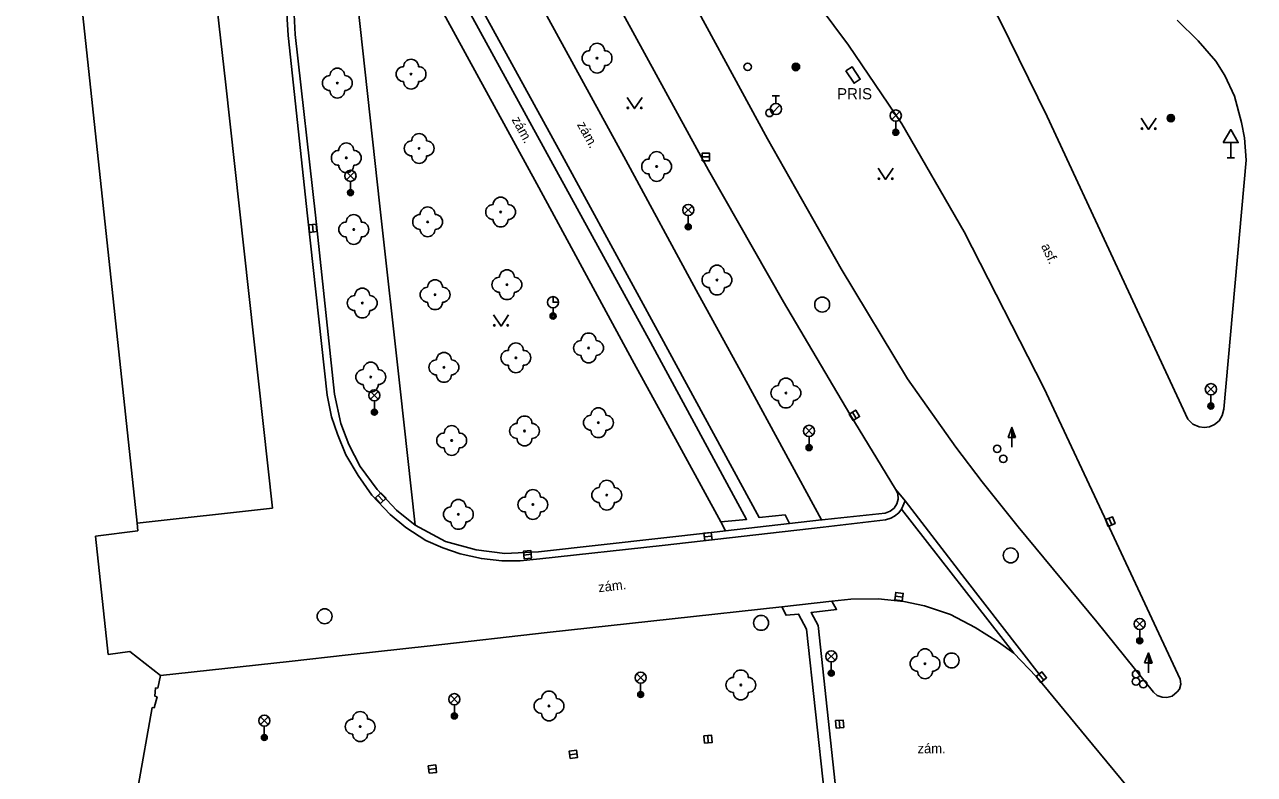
# Model space of a CAD drawing. Extents: x -598341 to -594502, y -1162301 to -1161406.
# Drawn here: x -597714.7 to -597632.3, y -1161626.1 to -1161575.8 of the extents above; entities that cross this region are included whole.
import ezdxf

# ---------------------------------------------------------------- set-up
doc = ezdxf.new("R2010")
doc.units = 0
for name, color, linetype in [('Vrstva 10', 7, 'Continuous'), ('Vrstva 11', 7, 'Continuous'), ('Vrstva 22', 7, 'Continuous'), ('Vrstva 24', 7, 'Continuous'), ('Vrstva 25', 7, 'Continuous'), ('Vrstva 27', 7, 'Continuous'), ('Vrstva 28', 7, 'Continuous'), ('Vrstva 33', 7, 'Continuous'), ('Vrstva 34', 7, 'Continuous'), ('Vrstva 36', 7, 'Continuous'), ('Vrstva 40', 7, 'Continuous'), ('Vrstva 41', 7, 'Continuous'), ('Vrstva 5', 7, 'Continuous')]:
    doc.layers.add(name, color=color, linetype=linetype)

msp = doc.modelspace()

# ---------------------------------------------------------------- linework, layer by layer
at = {"layer": 'Vrstva 10'}
for p, q in [((-597636.78, -1161602.29), (-597646.2, -1161581.99)), ((-597632.87, -1161584.92), (-597634.37, -1161601.62))]:
    msp.add_line(p, q, dxfattribs=at)
for points in [[(-597656.36, -1161606.96), (-597659.42, -1161601.94), (-597663.88, -1161594.41), (-597668.9, -1161585.59), (-597675.27, -1161573.94), (-597680.54, -1161564.05), (-597683.22, -1161558.87), (-597685.33, -1161554.76), (-597687.08, -1161551.17), (-597687.88, -1161549.64)], [(-597639.08, -1161620.57), (-597642.88, -1161615.87), (-597648.14, -1161609.49), (-597650.57, -1161606.47), (-597652.32, -1161604.16), (-597655.57, -1161599.57), (-597660.01, -1161592.2), (-597664.94, -1161583.49), (-597671.35, -1161571.69), (-597676.51, -1161562.01), (-597679.11, -1161556.86), (-597681.15, -1161552.57)], [(-597637.29, -1161619.71), (-597642.03, -1161609.56), (-597646.42, -1161600.19), (-597651.76, -1161589.72), (-597655.95, -1161582.49), (-597659.52, -1161577.23), (-597662.52, -1161573.15), (-597670.61, -1161562.65), (-597678.56, -1161552.49)], [(-597696.59, -1161576.5), (-597696.66, -1161575.16), (-597696.64, -1161573.61), (-597696.52, -1161572.32), (-597696.31, -1161571.01), (-597695.96, -1161569.39), (-597695.44, -1161567.63)], [(-597646.2, -1161581.99), (-597649.35, -1161575.58), (-597652.72, -1161569.3)], [(-597637.51, -1161575.55), (-597636.09, -1161576.92), (-597634.92, -1161578.3), (-597634.31, -1161579.26), (-597633.65, -1161580.63), (-597633.2, -1161582.39), (-597632.99, -1161583.43), (-597632.87, -1161584.92)], [(-597693.95, -1161600.61), (-597695.23, -1161588.62), (-597696.59, -1161576.5)], [(-597688.54, -1161609.38), (-597689.79, -1161608.38), (-597691.1, -1161607), (-597692.23, -1161605.45), (-597693, -1161603.97), (-597693.52, -1161602.56), (-597693.95, -1161600.61)], [(-597636.78, -1161602.29), (-597636.44, -1161602.62), (-597636.02, -1161602.8), (-597635.7, -1161602.84), (-597635.34, -1161602.79), (-597634.99, -1161602.64), (-597634.69, -1161602.39), (-597634.48, -1161602.04), (-597634.37, -1161601.62)], [(-597657.05, -1161608.57), (-597656.73, -1161608.45), (-597656.46, -1161608.24), (-597656.28, -1161607.95), (-597656.19, -1161607.64), (-597656.22, -1161607.26), (-597656.36, -1161606.96)], [(-597661.29, -1161609.03), (-597660.46, -1161608.93), (-597657.05, -1161608.57)], [(-597680.28, -1161611.18), (-597682.54, -1161611.29), (-597684.47, -1161611.03), (-597686.51, -1161610.47), (-597688.54, -1161609.38)], [(-597663.46, -1161609.27), (-597667.76, -1161609.76)], [(-597661.32, -1161609.03), (-597663.46, -1161609.27)], [(-597661.29, -1161609.03), (-597661.32, -1161609.03)], [(-597667.76, -1161609.76), (-597668.7, -1161609.87), (-597672.08, -1161610.26), (-597680.28, -1161611.18)], [(-597660.63, -1161614.48), (-597663.99, -1161614.85)], [(-597659.36, -1161614.35), (-597660.63, -1161614.48)], [(-597659.36, -1161614.35), (-597657.52, -1161614.31), (-597655.81, -1161614.5), (-597654.42, -1161614.78), (-597652.69, -1161615.36), (-597651.04, -1161616.23), (-597649.47, -1161617.22), (-597648.44, -1161617.96)], [(-597663.99, -1161614.85), (-597671.33, -1161615.65), (-597679.7, -1161616.58), (-597687.53, -1161617.48), (-597693.03, -1161618.08), (-597696.99, -1161618.51), (-597705.6, -1161619.45)], [(-597648.44, -1161617.96), (-597646.95, -1161619.53)], [(-597610.91, -1161677.42), (-597615.12, -1161669.99), (-597619.69, -1161661.76), (-597621.87, -1161657.96), (-597626.47, -1161650), (-597632.47, -1161638.84), (-597635.09, -1161634.33), (-597636.33, -1161632.57), (-597638.15, -1161630.21), (-597639.32, -1161628.73), (-597643.16, -1161624.07), (-597646.55, -1161619.99), (-597646.95, -1161619.53)], [(-597639.08, -1161620.57), (-597638.83, -1161620.79), (-597638.5, -1161620.92), (-597638.2, -1161620.93), (-597637.84, -1161620.84), (-597637.51, -1161620.55), (-597637.35, -1161620.37), (-597637.26, -1161620.04), (-597637.29, -1161619.71)]]:
    msp.add_lwpolyline(points, dxfattribs=at)
at = {"layer": 'Vrstva 11'}
for points in [[(-597663.46, -1161609.27), (-597663.76, -1161608.68), (-597665.49, -1161608.87), (-597672.17, -1161596.58), (-597678.7, -1161584.61), (-597685.19, -1161572.76), (-597692.44, -1161559.58), (-597691.74, -1161557.52), (-597692.02, -1161557)], [(-597668.08, -1161609.16), (-597666.34, -1161609), (-597672.77, -1161597.11), (-597679.46, -1161584.95), (-597685.96, -1161573.07), (-597692.73, -1161560.67), (-597693.42, -1161562.71), (-597693.7, -1161562.22)], [(-597669.73, -1161593.64), (-597674.43, -1161584.92), (-597680.24, -1161574.32), (-597685.26, -1161565.17), (-597687.25, -1161561.52)], [(-597697.05, -1161576.58), (-597697.11, -1161575.47), (-597697.09, -1161573.66), (-597696.94, -1161572.13), (-597696.71, -1161570.61), (-597696.34, -1161568.94), (-597695.82, -1161567.29)], [(-597668.08, -1161609.16), (-597671.75, -1161602.42), (-597673.87, -1161598.54), (-597680.39, -1161586.52), (-597686.5, -1161575.37), (-597690.54, -1161567.98), (-597692.96, -1161569.3), (-597692.22, -1161575.97)], [(-597694.44, -1161600.67), (-597695.75, -1161588.66), (-597697.05, -1161576.58)], [(-597688.54, -1161609.38), (-597689.56, -1161600.24), (-597690.92, -1161588), (-597692.22, -1161575.97)], [(-597661.32, -1161609.03), (-597666.38, -1161599.73), (-597669.73, -1161593.64)], [(-597680.19, -1161611.64), (-597681.51, -1161611.78), (-597682.73, -1161611.78), (-597684.11, -1161611.62), (-597685.54, -1161611.31), (-597686.69, -1161610.91), (-597687.82, -1161610.4), (-597689.16, -1161609.55), (-597690.21, -1161608.66), (-597691.45, -1161607.37), (-597692.37, -1161606.06), (-597693.19, -1161604.67), (-597693.75, -1161603.29), (-597694.15, -1161602.12), (-597694.44, -1161600.67)], [(-597655.73, -1161607.76), (-597656.36, -1161606.96)], [(-597655.96, -1161608.31), (-597655.73, -1161607.76)], [(-597646.74, -1161619.37), (-597651.69, -1161612.98), (-597655.73, -1161607.76)], [(-597657.04, -1161609.02), (-597656.68, -1161608.92), (-597656.44, -1161608.79), (-597656.15, -1161608.55), (-597655.96, -1161608.31)], [(-597648.44, -1161617.96), (-597655.96, -1161608.31)], [(-597657.04, -1161609.02), (-597661.22, -1161609.51), (-597672.01, -1161610.74), (-597680.19, -1161611.64)], [(-597667.76, -1161609.76), (-597668.08, -1161609.16)], [(-597659.74, -1161632.93), (-597661.55, -1161616.11), (-597662.02, -1161615.24), (-597660.32, -1161615.03), (-597660.63, -1161614.48)], [(-597659.74, -1161632.93), (-597660.53, -1161632.96), (-597662.33, -1161616.35), (-597662.86, -1161615.34), (-597663.7, -1161615.42), (-597663.99, -1161614.85)], [(-597646.95, -1161619.53), (-597646.74, -1161619.37)]]:
    msp.add_lwpolyline(points, dxfattribs=at)
at = {"layer": 'Vrstva 22'}
for centre in [(-597676.36, -1161578.09), (-597693.76, -1161579.76), (-597688.82, -1161579.16), (-597693.16, -1161584.77), (-597688.28, -1161584.14), (-597672.37, -1161585.35), (-597682.82, -1161588.4), (-597692.66, -1161589.57), (-597687.71, -1161589.06), (-597668.33, -1161592.96), (-597687.21, -1161593.94), (-597682.4, -1161593.27), (-597692.09, -1161594.5), (-597676.93, -1161597.51), (-597686.62, -1161598.81), (-597681.8, -1161598.17), (-597691.52, -1161599.46), (-597663.71, -1161600.53), (-597676.27, -1161602.52), (-597686.1, -1161603.71), (-597681.22, -1161603.07), (-597675.71, -1161607.37), (-597685.65, -1161608.66), (-597680.66, -1161608), (-597654.39, -1161618.67), (-597666.73, -1161620.09), (-597679.58, -1161621.5), (-597692.23, -1161622.88)]:
    msp.add_circle(centre, 0.05, dxfattribs=at)
for centre, start, end in [((-597676.36, -1161577.59), 0, 180), ((-597688.82, -1161578.66), 0, 180), ((-597676.86, -1161578.09), 90, 270), ((-597675.86, -1161578.09), 270, 90), ((-597693.76, -1161579.26), 0, 180), ((-597689.32, -1161579.16), 90, 270), ((-597688.32, -1161579.16), 270, 90), ((-597676.36, -1161578.59), 180, 0), ((-597694.26, -1161579.76), 90, 270), ((-597693.26, -1161579.76), 270, 90), ((-597688.82, -1161579.66), 180, 0), ((-597693.76, -1161580.26), 180, 0), ((-597688.28, -1161583.64), 0, 180), ((-597693.16, -1161584.27), 0, 180), ((-597688.78, -1161584.14), 90, 270), ((-597687.78, -1161584.14), 270, 90), ((-597693.66, -1161584.77), 90, 270), ((-597692.66, -1161584.77), 270, 90), ((-597688.28, -1161584.64), 180, 0), ((-597672.37, -1161584.85), 0, 180), ((-597693.16, -1161585.27), 180, 0), ((-597672.87, -1161585.35), 90, 270), ((-597671.87, -1161585.35), 270, 90), ((-597672.37, -1161585.85), 180, 0), ((-597687.71, -1161588.56), 0, 180), ((-597683.32, -1161588.4), 90, 270), ((-597682.82, -1161587.9), 0, 180), ((-597682.32, -1161588.4), 270, 90), ((-597692.66, -1161589.07), 0, 180), ((-597688.21, -1161589.06), 90, 270), ((-597687.21, -1161589.06), 270, 90), ((-597682.82, -1161588.9), 180, 0), ((-597693.16, -1161589.57), 90, 270), ((-597692.16, -1161589.57), 270, 90), ((-597687.71, -1161589.56), 180, 0), ((-597692.66, -1161590.07), 180, 0), ((-597668.33, -1161592.46), 0, 180), ((-597687.21, -1161593.44), 0, 180), ((-597682.9, -1161593.27), 90, 270), ((-597682.4, -1161592.77), 0, 180), ((-597681.9, -1161593.27), 270, 90), ((-597668.83, -1161592.96), 90, 270), ((-597667.83, -1161592.96), 270, 90), ((-597692.09, -1161594), 0, 180), ((-597687.71, -1161593.94), 90, 270), ((-597686.71, -1161593.94), 270, 90), ((-597682.4, -1161593.77), 180, 0), ((-597668.33, -1161593.46), 180, 0), ((-597692.59, -1161594.5), 90, 270), ((-597691.59, -1161594.5), 270, 90), ((-597687.21, -1161594.44), 180, 0), ((-597692.09, -1161595), 180, 0), ((-597681.8, -1161597.67), 0, 180), ((-597677.43, -1161597.51), 90, 270), ((-597676.93, -1161597.01), 0, 180), ((-597676.43, -1161597.51), 270, 90), ((-597686.62, -1161598.31), 0, 180), ((-597682.3, -1161598.17), 90, 270), ((-597681.3, -1161598.17), 270, 90), ((-597676.93, -1161598.01), 180, 0), ((-597691.52, -1161598.96), 0, 180), ((-597687.12, -1161598.81), 90, 270), ((-597686.12, -1161598.81), 270, 90), ((-597681.8, -1161598.67), 180, 0), ((-597692.02, -1161599.46), 90, 270), ((-597691.02, -1161599.46), 270, 90), ((-597686.62, -1161599.31), 180, 0), ((-597663.71, -1161600.03), 0, 180), ((-597691.52, -1161599.96), 180, 0), ((-597664.21, -1161600.53), 90, 270), ((-597663.21, -1161600.53), 270, 90), ((-597663.71, -1161601.03), 180, 0), ((-597681.22, -1161602.57), 0, 180), ((-597676.77, -1161602.52), 90, 270), ((-597676.27, -1161602.02), 0, 180), ((-597675.77, -1161602.52), 270, 90), ((-597686.1, -1161603.21), 0, 180), ((-597681.72, -1161603.07), 90, 270), ((-597680.72, -1161603.07), 270, 90), ((-597686.6, -1161603.71), 90, 270), ((-597685.6, -1161603.71), 270, 90), ((-597681.22, -1161603.57), 180, 0), ((-597676.27, -1161603.02), 180, 0), ((-597686.1, -1161604.21), 180, 0), ((-597680.66, -1161607.5), 0, 180), ((-597676.21, -1161607.37), 90, 270), ((-597675.71, -1161606.87), 0, 180), ((-597675.21, -1161607.37), 270, 90), ((-597685.65, -1161608.16), 0, 180), ((-597681.16, -1161608), 90, 270), ((-597680.16, -1161608), 270, 90), ((-597675.71, -1161607.87), 180, 0), ((-597686.15, -1161608.66), 90, 270), ((-597685.15, -1161608.66), 270, 90), ((-597680.66, -1161608.5), 180, 0), ((-597685.65, -1161609.16), 180, 0), ((-597654.39, -1161618.17), 0, 180), ((-597654.89, -1161618.67), 90, 270), ((-597653.89, -1161618.67), 270, 90), ((-597666.73, -1161619.59), 0, 180), ((-597654.39, -1161619.17), 180, 0), ((-597667.23, -1161620.09), 90, 270), ((-597666.23, -1161620.09), 270, 90), ((-597680.08, -1161621.5), 90, 270), ((-597679.58, -1161621), 0, 180), ((-597679.08, -1161621.5), 270, 90), ((-597666.73, -1161620.59), 180, 0), ((-597692.23, -1161622.38), 0, 180), ((-597692.73, -1161622.88), 90, 270), ((-597691.73, -1161622.88), 270, 90), ((-597679.58, -1161622), 180, 0), ((-597692.23, -1161623.38), 180, 0)]:
    msp.add_arc(centre, 0.5, start, end, dxfattribs=at)
at = {"layer": 'Vrstva 24'}
msp.add_lwpolyline([(-597659.695, -1161578.942), (-597659.141, -1161579.775), (-597658.725, -1161579.498), (-597659.279, -1161578.665)], close=True, dxfattribs=at)
at = {"layer": 'Vrstva 25'}
for p, q in [((-597648.822, -1161603.508), (-597648.57, -1161602.834)), ((-597648.57, -1161603.508), (-597648.822, -1161603.508)), ((-597648.57, -1161604.16), (-597648.57, -1161603.51)), ((-597639.682, -1161618.618), (-597639.43, -1161617.944)), ((-597639.43, -1161618.618), (-597639.682, -1161618.618)), ((-597639.43, -1161619.27), (-597639.43, -1161618.62))]:
    msp.add_line(p, q, dxfattribs=at)
for points in [[(-597648.32, -1161603.51), (-597648.57, -1161603.51), (-597648.57, -1161602.834), (-597648.57, -1161602.834)], [(-597648.377, -1161603.47), (-597648.53, -1161603.47), (-597648.53, -1161603.057)], [(-597648.435, -1161603.43), (-597648.49, -1161603.43), (-597648.49, -1161603.281)], [(-597639.18, -1161618.62), (-597639.43, -1161618.62), (-597639.43, -1161617.944), (-597639.43, -1161617.944)], [(-597639.237, -1161618.58), (-597639.39, -1161618.58), (-597639.39, -1161618.167)], [(-597639.295, -1161618.54), (-597639.35, -1161618.54), (-597639.35, -1161618.391)]]:
    msp.add_lwpolyline(points, close=True, dxfattribs=at)
for centre, radius in [((-597663.04, -1161578.68), 0.25), ((-597663.04, -1161578.68), 0.2), ((-597663.04, -1161578.68), 0.15), ((-597663.04, -1161578.68), 0.1), ((-597663.04, -1161578.68), 0.05), ((-597637.92, -1161582.11), 0.25), ((-597637.92, -1161582.11), 0.2), ((-597637.92, -1161582.11), 0.15), ((-597637.92, -1161582.11), 0.1), ((-597637.92, -1161582.11), 0.05)]:
    msp.add_circle(centre, radius, dxfattribs=at)
at = {"layer": 'Vrstva 27'}
for p, q in [((-597669.32, -1161584.71), (-597668.82, -1161584.71)), ((-597695.426, -1161589.241), (-597695.374, -1161589.739)), ((-597659.25, -1161601.806), (-597658.992, -1161602.234)), ((-597691.021, -1161607.388), (-597690.679, -1161607.752)), ((-597642.074, -1161608.908), (-597641.886, -1161609.371)), ((-597669.179, -1161610.167), (-597668.681, -1161610.113)), ((-597681.269, -1161611.384), (-597680.771, -1161611.336)), ((-597656.378, -1161614.14), (-597655.882, -1161614.2)), ((-597646.758, -1161619.376), (-597646.442, -1161619.764)), ((-597660.131, -1161622.461), (-597660.089, -1161622.959)), ((-597668.951, -1161623.471), (-597668.909, -1161623.969)), ((-597678.198, -1161624.77), (-597677.702, -1161624.71)), ((-597687.638, -1161625.76), (-597687.142, -1161625.7))]:
    msp.add_line(p, q, dxfattribs=at)
for points in [[(-597669.32, -1161584.96), (-597668.82, -1161584.96), (-597668.82, -1161584.46), (-597669.32, -1161584.46)], [(-597695.674, -1161589.267), (-597695.623, -1161589.764), (-597695.126, -1161589.713), (-597695.177, -1161589.216)], [(-597659.464, -1161601.936), (-597659.206, -1161602.364), (-597658.778, -1161602.104), (-597659.036, -1161601.677)], [(-597691.203, -1161607.559), (-597690.861, -1161607.923), (-597690.497, -1161607.581), (-597690.839, -1161607.217)], [(-597642.305, -1161609.002), (-597642.117, -1161609.465), (-597641.654, -1161609.277), (-597641.842, -1161608.814)], [(-597669.151, -1161610.416), (-597668.654, -1161610.361), (-597668.709, -1161609.864), (-597669.206, -1161609.919)], [(-597681.245, -1161611.633), (-597680.747, -1161611.585), (-597680.795, -1161611.087), (-597681.293, -1161611.135)], [(-597656.408, -1161614.388), (-597655.912, -1161614.448), (-597655.852, -1161613.952), (-597656.348, -1161613.892)], [(-597646.952, -1161619.535), (-597646.635, -1161619.922), (-597646.248, -1161619.605), (-597646.565, -1161619.218)], [(-597660.38, -1161622.482), (-597660.338, -1161622.98), (-597659.84, -1161622.938), (-597659.882, -1161622.44)], [(-597669.2, -1161623.492), (-597669.158, -1161623.99), (-597668.66, -1161623.948), (-597668.702, -1161623.45)], [(-597678.168, -1161625.019), (-597677.671, -1161624.958), (-597677.732, -1161624.461), (-597678.229, -1161624.522)], [(-597687.608, -1161626.009), (-597687.111, -1161625.948), (-597687.172, -1161625.451), (-597687.669, -1161625.512)]]:
    msp.add_lwpolyline(points, close=True, dxfattribs=at)
for centre in [(-597661.28, -1161594.6), (-597648.65, -1161611.41), (-597694.61, -1161615.49), (-597665.37, -1161615.93), (-597652.61, -1161618.45)]:
    msp.add_circle(centre, 0.5, dxfattribs=at)
at = {"layer": 'Vrstva 28'}
for p, q in [((-597664.63, -1161580.625), (-597664.13, -1161580.625)), ((-597664.38, -1161581.125), (-597664.38, -1161580.625)), ((-597664.638, -1161581.772), (-597664.108, -1161581.242))]:
    msp.add_line(p, q, dxfattribs=at)
for centre, radius in [((-597666.27, -1161578.67), 0.25), ((-597664.81, -1161581.76), 0.25), ((-597664.38, -1161581.5), 0.375), ((-597649.56, -1161604.27), 0.25), ((-597649.15, -1161604.94), 0.25), ((-597640.25, -1161619.37), 0.25), ((-597640.26, -1161619.86), 0.25), ((-597639.77, -1161620.04), 0.25)]:
    msp.add_circle(centre, radius, dxfattribs=at)
at = {"layer": 'Vrstva 33'}
for p, q in [((-597656.615, -1161582.2), (-597656.085, -1161581.67)), ((-597656.615, -1161581.67), (-597656.085, -1161582.2)), ((-597656.35, -1161582.31), (-597656.35, -1161583.06)), ((-597693.145, -1161586.24), (-597692.615, -1161585.71)), ((-597693.145, -1161585.71), (-597692.615, -1161586.24)), ((-597692.88, -1161586.35), (-597692.88, -1161587.1)), ((-597670.515, -1161588.53), (-597669.985, -1161588)), ((-597670.515, -1161588), (-597669.985, -1161588.53)), ((-597670.25, -1161588.64), (-597670.25, -1161589.39)), ((-597679.31, -1161594.82), (-597679.31, -1161595.17)), ((-597691.545, -1161600.95), (-597691.015, -1161600.42)), ((-597691.545, -1161600.42), (-597691.015, -1161600.95)), ((-597635.505, -1161600.54), (-597634.975, -1161600.01)), ((-597635.505, -1161600.01), (-597634.975, -1161600.54)), ((-597691.28, -1161601.06), (-597691.28, -1161601.81)), ((-597635.24, -1161600.65), (-597635.24, -1161601.4)), ((-597662.425, -1161603.33), (-597661.895, -1161602.8)), ((-597662.425, -1161602.8), (-597661.895, -1161603.33)), ((-597662.16, -1161603.44), (-597662.16, -1161604.19)), ((-597640.275, -1161616.27), (-597639.745, -1161615.74)), ((-597640.275, -1161615.74), (-597639.745, -1161616.27)), ((-597640.01, -1161616.38), (-597640.01, -1161617.13)), ((-597660.935, -1161618.44), (-597660.405, -1161617.91)), ((-597660.935, -1161617.91), (-597660.405, -1161618.44)), ((-597660.67, -1161618.55), (-597660.67, -1161619.3)), ((-597673.705, -1161619.87), (-597673.175, -1161619.34)), ((-597673.705, -1161619.34), (-597673.175, -1161619.87)), ((-597673.44, -1161619.98), (-597673.44, -1161620.73)), ((-597686.185, -1161621.31), (-597685.655, -1161620.78)), ((-597686.185, -1161620.78), (-597685.655, -1161621.31)), ((-597685.92, -1161621.42), (-597685.92, -1161622.17)), ((-597698.915, -1161622.75), (-597698.385, -1161622.22)), ((-597698.915, -1161622.22), (-597698.385, -1161622.75)), ((-597698.65, -1161622.86), (-597698.65, -1161623.61))]:
    msp.add_line(p, q, dxfattribs=at)
msp.add_lwpolyline([(-597679.31, -1161594.07), (-597679.31, -1161594.445), (-597678.935, -1161594.445)], dxfattribs=at)
for centre, radius in [((-597656.35, -1161581.935), 0.375), ((-597656.35, -1161583.06), 0.2), ((-597656.35, -1161583.06), 0.145), ((-597656.35, -1161583.06), 0.0876), ((-597692.88, -1161585.975), 0.375), ((-597692.88, -1161587.1), 0.2), ((-597692.88, -1161587.1), 0.145), ((-597692.88, -1161587.1), 0.0876), ((-597670.25, -1161588.265), 0.375), ((-597670.25, -1161589.39), 0.2), ((-597670.25, -1161589.39), 0.145), ((-597670.25, -1161589.39), 0.0876), ((-597679.31, -1161594.445), 0.375), ((-597679.31, -1161595.37), 0.2), ((-597679.31, -1161595.37), 0.145), ((-597679.31, -1161595.37), 0.0876), ((-597691.28, -1161600.685), 0.375), ((-597635.24, -1161600.275), 0.375), ((-597635.24, -1161601.4), 0.2), ((-597635.24, -1161601.4), 0.145), ((-597635.24, -1161601.4), 0.0876), ((-597691.28, -1161601.81), 0.2), ((-597691.28, -1161601.81), 0.145), ((-597691.28, -1161601.81), 0.0876), ((-597662.16, -1161603.065), 0.375), ((-597662.16, -1161604.19), 0.2), ((-597662.16, -1161604.19), 0.145), ((-597662.16, -1161604.19), 0.0876), ((-597640.01, -1161616.005), 0.375), ((-597640.01, -1161617.13), 0.2), ((-597640.01, -1161617.13), 0.145), ((-597640.01, -1161617.13), 0.0876), ((-597660.67, -1161618.175), 0.375), ((-597673.44, -1161619.605), 0.375), ((-597660.67, -1161619.3), 0.2), ((-597660.67, -1161619.3), 0.145), ((-597660.67, -1161619.3), 0.0876), ((-597685.92, -1161621.045), 0.375), ((-597673.44, -1161620.73), 0.2), ((-597673.44, -1161620.73), 0.145), ((-597673.44, -1161620.73), 0.0876), ((-597698.65, -1161622.485), 0.375), ((-597685.92, -1161622.17), 0.2), ((-597685.92, -1161622.17), 0.145), ((-597685.92, -1161622.17), 0.0876), ((-597698.65, -1161623.61), 0.2), ((-597698.65, -1161623.61), 0.145), ((-597698.65, -1161623.61), 0.0876)]:
    msp.add_circle(centre, radius, dxfattribs=at)
at = {"layer": 'Vrstva 34'}
for p, q in [((-597633.91, -1161583.742), (-597633.91, -1161584.76)), ((-597634.16, -1161584.76), (-597633.66, -1161584.76))]:
    msp.add_line(p, q, dxfattribs=at)
msp.add_lwpolyline([(-597634.41, -1161583.742), (-597633.41, -1161583.742), (-597633.91, -1161582.876)], close=True, dxfattribs=at)
at = {"layer": 'Vrstva 36'}
for points in [[(-597674.35, -1161580.72), (-597673.85, -1161581.47), (-597673.35, -1161580.72)], [(-597639.91, -1161582.11), (-597639.41, -1161582.86), (-597638.91, -1161582.11)], [(-597657.53, -1161585.47), (-597657.03, -1161586.22), (-597656.53, -1161585.47)], [(-597683.29, -1161595.29), (-597682.79, -1161596.04), (-597682.29, -1161595.29)]]:
    msp.add_lwpolyline(points, dxfattribs=at)
for centre in [(-597674.3, -1161581.42), (-597673.4, -1161581.42), (-597639.86, -1161582.81), (-597638.961, -1161582.81), (-597657.479, -1161586.17), (-597656.58, -1161586.17), (-597683.24, -1161595.989), (-597682.341, -1161595.989)]:
    msp.add_circle(centre, 0.05, dxfattribs=at)
at = {"layer": 'Vrstva 5'}
for p, q in [((-597707.18, -1161609.26), (-597714.71, -1161538.75)), ((-597701.26, -1161579.67), (-597702.24, -1161570.86)), ((-597698.1, -1161608.24), (-597701.26, -1161579.67)), ((-597707.18, -1161609.26), (-597698.1, -1161608.24)), ((-597707.12, -1161609.77), (-597707.18, -1161609.26)), ((-597709.95, -1161610.11), (-597707.12, -1161609.77)), ((-597709.11, -1161618.04), (-597709.95, -1161610.11)), ((-597707.66, -1161617.84), (-597709.11, -1161618.04)), ((-597705.6, -1161619.45), (-597707.66, -1161617.84)), ((-597705.78, -1161620.31), (-597705.6, -1161619.45)), ((-597706.02, -1161621.63), (-597705.84, -1161620.88)), ((-597705.99, -1161620.85), (-597705.93, -1161620.29)), ((-597705.84, -1161620.88), (-597705.99, -1161620.85)), ((-597705.93, -1161620.29), (-597705.78, -1161620.31)), ((-597707.13, -1161627), (-597706.17, -1161621.6)), ((-597706.17, -1161621.6), (-597706.02, -1161621.63))]:
    msp.add_line(p, q, dxfattribs=at)

# ---------------------------------------------------------------- texts
at = {"layer": 'Vrstva 40'}
for s, rotation, p in [('zám.', 298.72195, (-597682.1, -1161582.21)), ('zám.', 298.72195, (-597677.72, -1161582.54)), ('asf.', 294.83479, (-597646.63, -1161590.68)), ('zám.', 6.44498, (-597676.25, -1161613.88))]:
    msp.add_text(s, height=0.65, rotation=rotation, dxfattribs=at).set_placement(p)
msp.add_text('zám.', height=0.65, dxfattribs=at).set_placement((-597654.89, -1161624.67))
at = {"layer": 'Vrstva 41'}
msp.add_text('PRIS', height=0.75, dxfattribs=at).set_placement((-597660.28, -1161580.85))

doc.saveas('drawing.dxf')
